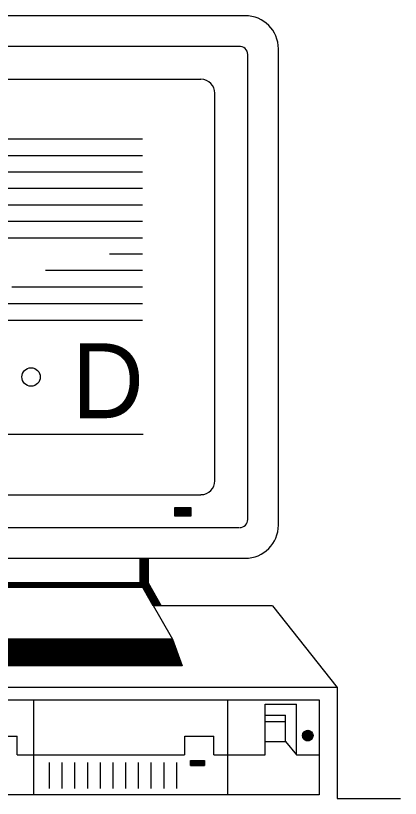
# Model space of a CAD drawing. Extents: x 22388.1 to 22405.7, y 22369.6 to 22390.4.
# Drawn here: x 22401.18 to 22401.435, y 22370.179 to 22370.697 of the extents above; entities that cross this region are included whole.
import ezdxf

# ---------------------------------------------------------------- set-up
doc = ezdxf.new("R2010")
doc.units = 0
for name, color, linetype in [('Level 2', 7, 'Continuous'), ('Level 25', 7, 'Continuous'), ('Level 3', 7, 'Continuous'), ('Level 5', 7, 'Continuous'), ('Level 7', 7, 'Continuous')]:
    doc.layers.add(name, color=color, linetype=linetype)

msp = doc.modelspace()

# ---------------------------------------------------------------- linework, layer by layer
at = {"layer": 'Level 2'}
for p, q in [((22400.98759, 22370.65488), (22401.30301, 22370.65488)), ((22401.31218, 22370.38909), (22401.31218, 22370.64572)), ((22400.98759, 22370.37993), (22401.30301, 22370.37993)), ((22401.28572, 22370.3713), (22401.29618, 22370.3713)), ((22401.28572, 22370.37101), (22401.29618, 22370.37101)), ((22401.28572, 22370.37068), (22401.29618, 22370.37068)), ((22401.28572, 22370.3703), (22401.29618, 22370.3703)), ((22401.28572, 22370.36997), (22401.29618, 22370.36997)), ((22401.28572, 22370.36968), (22401.29618, 22370.36968)), ((22401.28572, 22370.36934), (22401.29618, 22370.36934)), ((22401.28572, 22370.36901), (22401.29618, 22370.36901)), ((22401.28572, 22370.36868), (22401.29618, 22370.36868)), ((22401.28572, 22370.36834), (22401.29618, 22370.36834)), ((22401.28572, 22370.36801), (22401.29618, 22370.36801)), ((22401.28572, 22370.36768), (22401.29618, 22370.36768)), ((22401.28572, 22370.36738), (22401.29618, 22370.36738)), ((22401.28572, 22370.36701), (22401.29618, 22370.36701)), ((22401.28572, 22370.36668), (22401.29618, 22370.36668)), ((22401.28572, 22370.36638), (22401.29618, 22370.36638)), ((22401.28572, 22370.36605), (22401.29618, 22370.36605)), ((22401.26264, 22370.32163), (22401.26264, 22370.3378)), ((22401.26793, 22370.33768), (22401.26264, 22370.33768)), ((22401.26793, 22370.33734), (22401.26264, 22370.33734)), ((22401.26793, 22370.33705), (22401.26264, 22370.33705)), ((22401.26793, 22370.33668), (22401.26264, 22370.33668)), ((22401.26793, 22370.33634), (22401.26264, 22370.33634)), ((22401.26793, 22370.33601), (22401.26264, 22370.33601)), ((22401.26793, 22370.33572), (22401.26264, 22370.33572)), ((22401.26793, 22370.33538), (22401.26264, 22370.33538)), ((22401.26793, 22370.33501), (22401.26264, 22370.33501)), ((22401.26793, 22370.33468), (22401.26264, 22370.33468)), ((22401.26793, 22370.33438), (22401.26264, 22370.33438)), ((22401.26793, 22370.33405), (22401.26264, 22370.33405)), ((22401.26793, 22370.33372), (22401.26264, 22370.33372)), ((22401.26793, 22370.33338), (22401.26264, 22370.33338)), ((22401.26793, 22370.33305), (22401.26264, 22370.33305)), ((22401.26793, 22370.33272), (22401.26264, 22370.33272)), ((22401.26793, 22370.33238), (22401.26264, 22370.33238)), ((22401.26793, 22370.33209), (22401.26264, 22370.33209)), ((22401.26793, 22370.33172), (22401.26264, 22370.33172)), ((22401.26793, 22370.33138), (22401.26264, 22370.33138)), ((22401.26793, 22370.33109), (22401.26264, 22370.33109)), ((22401.26793, 22370.33076), (22401.26264, 22370.33076)), ((22401.26793, 22370.33043), (22401.26264, 22370.33043)), ((22401.26793, 22370.33005), (22401.26264, 22370.33005)), ((22401.26793, 22370.32976), (22401.26264, 22370.32976)), ((22401.26793, 22370.32943), (22401.26264, 22370.32943)), ((22401.26793, 22370.32909), (22401.26264, 22370.32909)), ((22401.26793, 22370.3288), (22401.26264, 22370.3288)), ((22401.26793, 22370.32843), (22401.26264, 22370.32843)), ((22401.26793, 22370.32809), (22401.26264, 22370.32809)), ((22401.26793, 22370.32776), (22401.26264, 22370.32776)), ((22401.26793, 22370.32747), (22401.26264, 22370.32747)), ((22401.26793, 22370.32713), (22401.26264, 22370.32713)), ((22401.26793, 22370.32676), (22401.26264, 22370.32676)), ((22401.26793, 22370.32643), (22401.26264, 22370.32643)), ((22401.26793, 22370.32613), (22401.26264, 22370.32613)), ((22401.26793, 22370.3258), (22401.26264, 22370.3258)), ((22401.26793, 22370.32547), (22401.26264, 22370.32547)), ((22401.26272, 22370.32155), (22401.1453, 22370.32155)), ((22401.26293, 22370.32122), (22401.1453, 22370.32122)), ((22401.26309, 22370.32088), (22401.1453, 22370.32088)), ((22401.26326, 22370.32055), (22401.1453, 22370.32055)), ((22401.26793, 22370.32513), (22401.26264, 22370.32513)), ((22401.26793, 22370.3248), (22401.26264, 22370.3248)), ((22401.26793, 22370.32447), (22401.26264, 22370.32447)), ((22401.26793, 22370.32413), (22401.26264, 22370.32413)), ((22401.26793, 22370.32384), (22401.26264, 22370.32384)), ((22401.26793, 22370.32347), (22401.26264, 22370.32347)), ((22401.26793, 22370.32313), (22401.26264, 22370.32313)), ((22401.26793, 22370.32284), (22401.26264, 22370.32284)), ((22401.26793, 22370.32251), (22401.26264, 22370.32251)), ((22401.26793, 22370.32218), (22401.26264, 22370.32218)), ((22401.26793, 22370.3218), (22401.26264, 22370.3218)), ((22401.26264, 22370.32163), (22401.28409, 22370.28426)), ((22401.26801, 22370.32151), (22401.26272, 22370.32151)), ((22401.26818, 22370.32118), (22401.26293, 22370.32118)), ((22401.26843, 22370.32084), (22401.26309, 22370.32084)), ((22401.26859, 22370.32055), (22401.26334, 22370.32055)), ((22401.26347, 22370.32022), (22401.1453, 22370.32022)), ((22401.26364, 22370.31988), (22401.1453, 22370.31988)), ((22401.26384, 22370.31955), (22401.1453, 22370.31955)), ((22401.26405, 22370.31926), (22401.1453, 22370.31926)), ((22401.26426, 22370.31888), (22401.1453, 22370.31888)), ((22401.26443, 22370.31855), (22401.1453, 22370.31855)), ((22401.26447, 22370.31851), (22401.1453, 22370.31851)), ((22401.26876, 22370.32018), (22401.26351, 22370.32018)), ((22401.26897, 22370.31984), (22401.26368, 22370.31984)), ((22401.26914, 22370.31951), (22401.26389, 22370.31951)), ((22401.26934, 22370.31922), (22401.26405, 22370.31922)), ((22401.26955, 22370.31888), (22401.26426, 22370.31888)), ((22401.26968, 22370.31851), (22401.26443, 22370.31851)), ((22401.26993, 22370.31818), (22401.26459, 22370.31818)), ((22401.27009, 22370.31788), (22401.26484, 22370.31788)), ((22401.2703, 22370.31755), (22401.26501, 22370.31755)), ((22401.27047, 22370.31722), (22401.26522, 22370.31722)), ((22401.27068, 22370.31688), (22401.26539, 22370.31688)), ((22401.27084, 22370.31655), (22401.26555, 22370.31655)), ((22401.27105, 22370.31622), (22401.26576, 22370.31622)), ((22401.27126, 22370.31588), (22401.26597, 22370.31588)), ((22401.27143, 22370.31559), (22401.26614, 22370.31559)), ((22401.27164, 22370.31522), (22401.26634, 22370.31522)), ((22401.2718, 22370.31488), (22401.26655, 22370.31488)), ((22401.27197, 22370.31459), (22401.26672, 22370.31459)), ((22401.27218, 22370.31426), (22401.26689, 22370.31426)), ((22401.27234, 22370.31393), (22401.26709, 22370.31393)), ((22401.27259, 22370.31355), (22401.26726, 22370.31355)), ((22401.27276, 22370.31326), (22401.26751, 22370.31326)), ((22401.27297, 22370.31293), (22401.26768, 22370.31293)), ((22401.27314, 22370.31259), (22401.26784, 22370.31259)), ((22401.2733, 22370.3123), (22401.26805, 22370.3123)), ((22401.27351, 22370.31193), (22401.26822, 22370.31193)), ((22401.27368, 22370.31159), (22401.26843, 22370.31159)), ((22401.27389, 22370.31126), (22401.26859, 22370.31126)), ((22401.27409, 22370.31097), (22401.26876, 22370.31097)), ((22401.27426, 22370.31063), (22401.26901, 22370.31063)), ((22401.27447, 22370.31026), (22401.26918, 22370.31026)), ((22401.27464, 22370.30993), (22401.26939, 22370.30993)), ((22401.27484, 22370.30963), (22401.26955, 22370.30963)), ((22401.27501, 22370.3093), (22401.26976, 22370.3093)), ((22401.27518, 22370.30897), (22401.26993, 22370.30897)), ((22401.27543, 22370.30863), (22401.27009, 22370.30863)), ((22401.27559, 22370.3083), (22401.2703, 22370.3083)), ((22401.2758, 22370.30797), (22401.27051, 22370.30797)), ((22401.27597, 22370.30763), (22401.27072, 22370.30763)), ((22401.27618, 22370.30734), (22401.27089, 22370.30734)), ((22401.27634, 22370.30697), (22401.27105, 22370.30697)), ((22401.27651, 22370.30663), (22401.27126, 22370.30663)), ((22401.28409, 22370.28426), (22401.1453, 22370.28426)), ((22401.28414, 22370.28413), (22401.1453, 22370.28413)), ((22401.28426, 22370.2838), (22401.1453, 22370.2838)), ((22401.28443, 22370.28351), (22401.1453, 22370.28351)), ((22401.28451, 22370.28313), (22401.1453, 22370.28313)), ((22401.28464, 22370.2828), (22401.1453, 22370.2828)), ((22401.28476, 22370.28251), (22401.1453, 22370.28251)), ((22401.28489, 22370.28218), (22401.1453, 22370.28218)), ((22401.28501, 22370.28184), (22401.1453, 22370.28184)), ((22401.28509, 22370.28147), (22401.1453, 22370.28147)), ((22401.28522, 22370.28118), (22401.1453, 22370.28118)), ((22401.28539, 22370.28084), (22401.1453, 22370.28084)), ((22401.28551, 22370.28051), (22401.1453, 22370.28051)), ((22401.28559, 22370.28022), (22401.1453, 22370.28022)), ((22401.28572, 22370.27984), (22401.1453, 22370.27984)), ((22401.28589, 22370.27951), (22401.1453, 22370.27951)), ((22401.28597, 22370.27918), (22401.1453, 22370.27918)), ((22401.28609, 22370.27888), (22401.1453, 22370.27888)), ((22401.28618, 22370.27855), (22401.1453, 22370.27855)), ((22401.28634, 22370.27818), (22401.1453, 22370.27818)), ((22401.28647, 22370.27784), (22401.1453, 22370.27784)), ((22401.28659, 22370.27755), (22401.1453, 22370.27755)), ((22401.28672, 22370.27722), (22401.1453, 22370.27722)), ((22401.28684, 22370.27688), (22401.1453, 22370.27688)), ((22401.28693, 22370.27655), (22401.1453, 22370.27655)), ((22401.28705, 22370.27622), (22401.1453, 22370.27622)), ((22401.28722, 22370.27588), (22401.1453, 22370.27588)), ((22401.2873, 22370.27555), (22401.1453, 22370.27555)), ((22401.28743, 22370.27526), (22401.1453, 22370.27526)), ((22401.28755, 22370.27488), (22401.1453, 22370.27488)), ((22401.28772, 22370.27455), (22401.1453, 22370.27455)), ((22401.2878, 22370.27426), (22401.1453, 22370.27426)), ((22401.28793, 22370.27393), (22401.1453, 22370.27393)), ((22401.28801, 22370.27359), (22401.1453, 22370.27359)), ((22401.28818, 22370.27322), (22401.1453, 22370.27322)), ((22401.2883, 22370.27293), (22401.1453, 22370.27293)), ((22401.28839, 22370.27259), (22401.1453, 22370.27259)), ((22401.28855, 22370.27226), (22401.1453, 22370.27226)), ((22401.28868, 22370.27197), (22401.1453, 22370.27197)), ((22401.28876, 22370.27159), (22401.1453, 22370.27159)), ((22401.28889, 22370.27126), (22401.1453, 22370.27126)), ((22401.28905, 22370.27093), (22401.1453, 22370.27093)), ((22401.28914, 22370.27063), (22401.1453, 22370.27063)), ((22401.28926, 22370.2703), (22401.1453, 22370.2703)), ((22401.28939, 22370.26993), (22401.1453, 22370.26993)), ((22401.28951, 22370.26959), (22401.1453, 22370.26959)), ((22401.28964, 22370.2693), (22401.1453, 22370.2693)), ((22401.28976, 22370.26897), (22401.1453, 22370.26897)), ((22401.28984, 22370.26863), (22401.1453, 22370.26863)), ((22401.29001, 22370.2683), (22401.1453, 22370.2683)), ((22401.29014, 22370.26797), (22401.1453, 22370.26797)), ((22401.29022, 22370.26763), (22401.1453, 22370.26763)), ((22401.29039, 22370.2673), (22401.1453, 22370.2673)), ((22401.29051, 22370.26701), (22401.1453, 22370.26701)), ((22401.29059, 22370.26672), (22401.1453, 22370.26672)), ((22401.19239, 22370.18134), (22401.19239, 22370.24405)), ((22401.32076, 22370.18134), (22401.32076, 22370.24405)), ((22401.34555, 22370.20772), (22401.34555, 22370.24134)), ((22401.34555, 22370.24134), (22401.36626, 22370.24134)), ((22401.36626, 22370.20772), (22401.36626, 22370.24134)), ((22401.34555, 22370.23405), (22401.35893, 22370.23405)), ((22401.35893, 22370.21659), (22401.35893, 22370.23405)), ((22401.34555, 22370.22984), (22401.35893, 22370.22984)), ((22401.37068, 22370.22213), (22401.3768, 22370.22213)), ((22401.37084, 22370.22251), (22401.37659, 22370.22251)), ((22401.37114, 22370.2228), (22401.3763, 22370.2228)), ((22401.37143, 22370.22313), (22401.37597, 22370.22313)), ((22401.37189, 22370.22347), (22401.37551, 22370.22347)), ((22401.37268, 22370.22376), (22401.3748, 22370.22376)), ((22401.15647, 22370.22009), (22401.18118, 22370.22009)), ((22401.18118, 22370.20772), (22401.18118, 22370.22009)), ((22401.29222, 22370.22009), (22401.31155, 22370.22009)), ((22401.29222, 22370.20772), (22401.29222, 22370.22009)), ((22401.31155, 22370.20772), (22401.31155, 22370.22009)), ((22401.37022, 22370.22047), (22401.37722, 22370.22047)), ((22401.37026, 22370.22084), (22401.37718, 22370.22084)), ((22401.37026, 22370.22018), (22401.37722, 22370.22018)), ((22401.3703, 22370.22118), (22401.37714, 22370.22118)), ((22401.3703, 22370.21984), (22401.37714, 22370.21984)), ((22401.37034, 22370.21951), (22401.37709, 22370.21951)), ((22401.37039, 22370.22147), (22401.37709, 22370.22147)), ((22401.37047, 22370.2218), (22401.37693, 22370.2218)), ((22401.37047, 22370.21918), (22401.37693, 22370.21918)), ((22401.37064, 22370.21884), (22401.3768, 22370.21884)), ((22401.3708, 22370.21851), (22401.37664, 22370.21851)), ((22401.37109, 22370.21818), (22401.37634, 22370.21818)), ((22401.37139, 22370.21788), (22401.37601, 22370.21788)), ((22401.37184, 22370.21755), (22401.37564, 22370.21755)), ((22401.37251, 22370.21718), (22401.37493, 22370.21718)), ((22401.34555, 22370.21659), (22401.35893, 22370.21659)), ((22401.35893, 22370.21659), (22401.36626, 22370.20772)), ((22401.18118, 22370.20772), (22401.29209, 22370.20772)), ((22401.31155, 22370.20772), (22401.34555, 22370.20772)), ((22401.36626, 22370.20772), (22401.38118, 22370.20772)), ((22401.29601, 22370.20405), (22401.30543, 22370.20405)), ((22401.29601, 22370.20376), (22401.30543, 22370.20376)), ((22401.29601, 22370.20338), (22401.30543, 22370.20338)), ((22401.29601, 22370.20305), (22401.30543, 22370.20305)), ((22401.29601, 22370.20276), (22401.30543, 22370.20276)), ((22401.29601, 22370.20243), (22401.30543, 22370.20243)), ((22401.29601, 22370.20209), (22401.30543, 22370.20209)), ((22401.29601, 22370.20172), (22401.30543, 22370.20172)), ((22401.29601, 22370.20143), (22401.30543, 22370.20143)), ((22401.29601, 22370.20109), (22401.30543, 22370.20109)), ((22401.29601, 22370.20076), (22401.30543, 22370.20076))]:
    msp.add_line(p, q, dxfattribs=at)
for points in [[(22401.28572, 22370.37155), (22401.29618, 22370.37155), (22401.29618, 22370.36576), (22401.28572, 22370.36576)], [(22401.26793, 22370.3378), (22401.26793, 22370.32163), (22401.27672, 22370.30638), (22401.27143, 22370.30638), (22401.26264, 22370.32163), (22401.26264, 22370.3378)], [(22401.26264, 22370.32163), (22401.26447, 22370.31851), (22401.1453, 22370.31851), (22401.1453, 22370.32163)], [(22401.28409, 22370.28426), (22401.29059, 22370.26672), (22401.1453, 22370.26672), (22401.1453, 22370.28426)], [(22400.91018, 22370.24405), (22401.38118, 22370.24405), (22401.38118, 22370.18134), (22400.91018, 22370.18134)], [(22401.29601, 22370.20405), (22401.30543, 22370.20405), (22401.30543, 22370.20076), (22401.29601, 22370.20076)]]:
    msp.add_lwpolyline(points, close=True, dxfattribs=at)
for centre, radius in [((22401.1905, 22370.45783), 0.0061), ((22401.37372, 22370.22047), 0.0035)]:
    msp.add_circle(centre, radius, dxfattribs=at)
for centre, start, end in [((22401.303, 22370.64571), 0, 90), ((22401.303, 22370.3891), 270, 0)]:
    msp.add_arc(centre, 0.00916, start, end, dxfattribs=at)
at = {"layer": 'Level 25'}
msp.add_line((22401.26264, 22370.32163), (22401.1453, 22370.32163), dxfattribs=at)
at = {"layer": 'Level 3'}
for p, q in [((22400.9583, 22370.69701), (22401.3323, 22370.69701)), ((22400.96209, 22370.67672), (22401.32814, 22370.67672)), ((22401.3543, 22370.3598), (22401.3543, 22370.67501)), ((22401.33401, 22370.36363), (22401.33401, 22370.67122)), ((22400.96209, 22370.35813), (22401.32814, 22370.35813)), ((22400.9583, 22370.3378), (22401.3323, 22370.3378))]:
    msp.add_line(p, q, dxfattribs=at)
for centre, radius, start, end in [((22401.33229, 22370.675), 0.022, 0, 90), ((22401.3285, 22370.67121), 0.0055, 0, 93.8704), ((22401.3285, 22370.36361), 0.0055, 270, 0), ((22401.33229, 22370.35981), 0.022, 270, 0)]:
    msp.add_arc(centre, radius, start, end, dxfattribs=at)
at = {"layer": 'Level 5'}
for p, q in [((22401.02847, 22370.61543), (22401.2643, 22370.61543)), ((22401.16814, 22370.60451), (22401.2643, 22370.60451)), ((22401.16814, 22370.59363), (22401.2643, 22370.59363)), ((22401.16814, 22370.58276), (22401.2643, 22370.58276)), ((22401.16814, 22370.57184), (22401.2643, 22370.57184)), ((22401.16814, 22370.56093), (22401.2643, 22370.56093)), ((22401.02847, 22370.55001), (22401.2643, 22370.55001)), ((22401.26426, 22370.53918), (22401.24247, 22370.53918)), ((22401.26426, 22370.52826), (22401.20001, 22370.52826)), ((22401.26426, 22370.51738), (22401.17768, 22370.51738)), ((22401.02847, 22370.50647), (22401.2643, 22370.50647)), ((22401.02847, 22370.49555), (22401.2643, 22370.49555)), ((22401.02847, 22370.41993), (22401.26472, 22370.41993)), ((22401.26793, 22370.32163), (22401.26793, 22370.3378)), ((22401.26793, 22370.32163), (22401.27672, 22370.30638)), ((22401.35034, 22370.30638), (22401.27143, 22370.30638)), ((22401.35034, 22370.30638), (22401.39318, 22370.25234)), ((22401.39318, 22370.25234), (22401.1453, 22370.25234)), ((22401.39318, 22370.25234), (22401.39318, 22370.17893)), ((22401.39318, 22370.17893), (22401.43505, 22370.17893))]:
    msp.add_line(p, q, dxfattribs=at)
at = {"layer": 'Level 7'}
for p, q in [((22401.20272, 22370.18534), (22401.20272, 22370.20259)), ((22401.21114, 22370.18534), (22401.21114, 22370.20259)), ((22401.21955, 22370.18534), (22401.21955, 22370.20259)), ((22401.22797, 22370.18534), (22401.22797, 22370.20259)), ((22401.23643, 22370.18534), (22401.23643, 22370.20259)), ((22401.24484, 22370.18534), (22401.24484, 22370.20259)), ((22401.2533, 22370.18534), (22401.2533, 22370.20259)), ((22401.26172, 22370.18534), (22401.26172, 22370.20259)), ((22401.27009, 22370.18534), (22401.27009, 22370.20259)), ((22401.27855, 22370.18534), (22401.27855, 22370.20259)), ((22401.28697, 22370.18534), (22401.28697, 22370.20259))]:
    msp.add_line(p, q, dxfattribs=at)

# ---------------------------------------------------------------- texts
at = {"layer": 'Level 5'}
msp.add_text('D', height=0.04959, dxfattribs=at).set_placement((22401.21734, 22370.43055))

doc.saveas('drawing.dxf')
